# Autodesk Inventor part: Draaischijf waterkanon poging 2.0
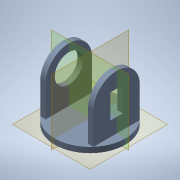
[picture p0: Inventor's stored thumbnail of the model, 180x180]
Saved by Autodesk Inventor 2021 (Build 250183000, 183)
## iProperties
Manager: Pierloot J.
Company: Emmaüs Bovenbouw Aalter
Created: 2015-08
Part Number: Draaischijf waterkanon poging 2.0
Material: S235
Catalog Web Link: http://emmausbovenbouw.op-weg.be/
Vendor: Emmaüsinstituut Bovenbouw Aalter
Document SubType Name: Modeling
Designer: Pierlootj
Engineer: Pierloot J.
Manufacturer: Standard
Standards Organization: Custom
Density: 7.86 g/cm^3
Appearance: Light Steel Blue
Title: Algemene titel
Subject: Specifieke titel
Author: Pierlootj
Keywords: Ruwe Ø xxxxx
Comments: Opmerking
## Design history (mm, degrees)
sketch "Sketch14"
  geometry: L1 (0, 0)-(-24.5, 0); L2 (-24.5, 0)-(24.5, 0); L3 (-24.5, 0)-(-24.5, -21.354); L4 (-24.5, 21.354)-(-19.5, 21.354); L5 (-19.5, 21.354)-(-19.5, -21.354); L6 (-19.5, -21.354)-(-24.5, -21.354); L7 (-24.5, -21.354)-(-24.5, 21.354); L8 (0, 27.067)-(0, -27.009); L9 (19.5, -21.354)-(24.5, -21.354); L10 (19.5, 21.354)-(19.5, -21.354); L11 (24.5, -21.354)-(24.5, 21.354); L12 (24.5, 21.354)-(19.5, 21.354); A1 r 32.5 centre (0, 0) between (-24.5, -21.354) and (-24.5, 21.354)
  constraints: 24 end point, 4 symmetric about line, 2 horizontal, 2 parallel, 2 point on circle, 2 vertical, 1 centre point, 1 coincident, 1 perpendicular, 1 point on line
  dimensions: "d105" = 24.5 distance of L1.start L1.end; "d106" = 49 distance of L1.end L2.end; "d107" = 65 diameter of A1; "d108" = 5 distance of L5.end L6.end
extrude "Extrusion12" new body sketch "Sketch14" distance "d109" = 5; taper "d110" = 0 deg
sketch "Sketch15"
  geometry: L1 (0, 0)-(-24.5, 0); L2 (-24.5, 0)-(24.5, 0); L3 (-24.5, 0)-(-24.5, -21.354); L4 (-24.5, 21.354)-(-19.5, 21.354); L5 (-19.5, 21.354)-(-19.5, -21.354); L6 (-19.5, -21.354)-(-24.5, -21.354); L7 (-24.5, -21.354)-(-24.5, 21.354); L8 (0, 27.067)-(0, -27.009); L9 (19.5, -21.354)-(24.5, -21.354); L10 (19.5, 21.354)-(19.5, -21.354); L11 (24.5, -21.354)-(24.5, 21.354); L12 (24.5, 21.354)-(19.5, 21.354); 1 further point
  constraints: 24 end point, 4 symmetric about line, 2 horizontal, 2 parallel, 2 vertical, 1 perpendicular, 1 point on line
  dimensions: "d111" = 24.5 distance of L1.start L1.end; "d112" = 49 distance of L1.end L2.end; "d114" = 5 distance of L5.end L6.end
extrude "Extrusion13" join sketch "Sketch15" distance "d115" = 50; taper "d116" = 0 deg
fillet "Fillet5" dims "d117" = 21.3
sketch "Sketch16"
  geometry: L1 (0, 0)-(0, 42.708) reference; L2 (0, 21.354)-(30, 21.354); C1 r 13 at (30, 21.354); 1 further point
  constraints: 2 end point, 1 centre point, 1 coincident, 1 horizontal, 1 midpoint
  dimensions: "d118" = 30 distance of L2.start L2.end; "d130" = 26 diameter of C1
extrude "Extrusion14" cut sketch "Sketch16" distance "d120" = 5; taper "d121" = 0 deg
sketch "Sketch17"
  geometry: L1 (0, 42.708)-(0, 0) reference; L2 (0, 21.354)-(-30, 21.354); L3 (-35.75, 15.604)-(-13.25, 15.604); L4 (-13.25, 15.604)-(-13.25, 27.104); L5 (-13.25, 27.104)-(-35.75, 27.104); L6 (-35.75, 27.104)-(-35.75, 15.604); C1 r 5.75 at (-30, 21.354); 1 further point
  constraints: 10 end point, 2 horizontal, 2 parallel, 1 centre point, 1 coincident, 1 midpoint, 1 perpendicular
  dimensions: "d122" = 30 distance of L2.start L2.end; "d123" = 11.5 diameter of C1; "d124" = 22.5 distance of L5.end L4.end
extrude "Extrusion15" cut sketch "Sketch17" distance "d125" = 5; taper "d126" = 0 deg
sketch "Sketch18"
  geometry: C1 r 2.5 at (0, 0); 1 further point
  constraints: 1 centre point, 1 coincident
  dimensions: "d127" = 5 diameter of C1
extrude "Extrusion16" cut sketch "Sketch18" distance "d128" = 3.5; taper "d129" = 0 deg
body "Solid6"
